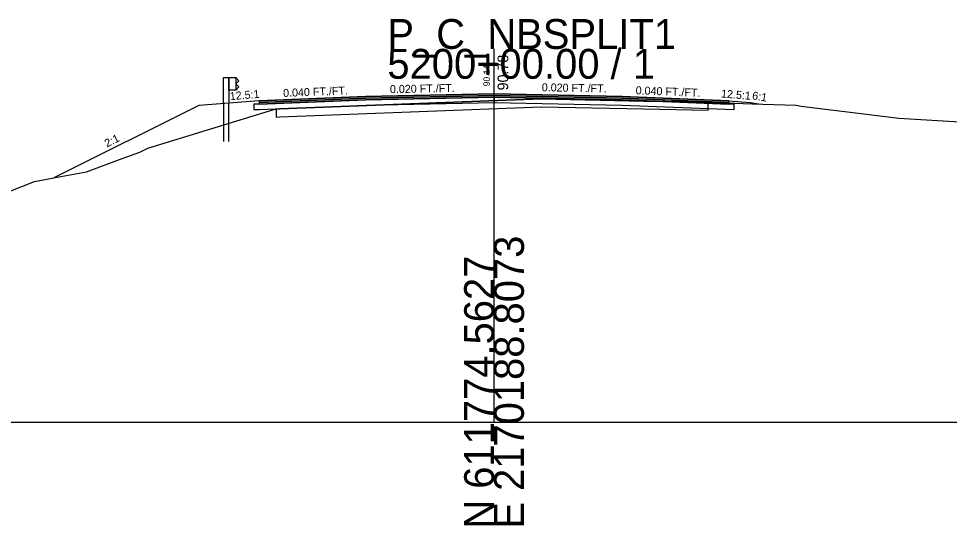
# Model space of a CAD drawing. Extents: x -26 to 1303, y -3010 to 12038.
# Drawn here: x 1105.4 to 1192.7, y 990.3 to 1037.8 of the extents above; entities that cross this region are included whole.
import ezdxf

# ---------------------------------------------------------------- set-up
doc = ezdxf.new("R2010")
doc.units = 0
for name, color, linetype in [('RD_GPK_XS_Cell', 7, 'Continuous'), ('RD_PD_Final_TrvlWay', 7, 'Continuous'), ('RD_XS_Base', 7, 'Continuous'), ('RD_XS_ExGround', 7, 'Continuous'), ('RD_XS_ExPaveRet', 7, 'Continuous'), ('RD_XS_GR', 7, 'Continuous'), ('RD_XS_Greenside', 7, 'Continuous'), ('RD_XS_Pave', 7, 'Continuous'), ('RD_XS_PaveOvlay_CP', 7, 'Continuous'), ('RD_XS_TieSlope', 7, 'Continuous'), ('RD_XS_TX_Elev_EX', 7, 'Continuous'), ('RD_XS_TX_Elev_PR', 7, 'Continuous'), ('RD_XS_TX_ShdSlope', 7, 'Continuous'), ('RD_XS_TX_Slope', 7, 'Continuous')]:
    doc.layers.add(name, color=color, linetype=linetype)

msp = doc.modelspace()

# ---------------------------------------------------------------- linework, layer by layer
at = {"layer": 'RD_GPK_XS_Cell'}
for p, q in [((1150, 1000), (1150, 1035)), ((1000, 1000), (1150, 1000)), ((1150, 1000), (1300, 1000))]:
    msp.add_line(p, q, dxfattribs=at)
at = {"layer": 'RD_PD_Final_TrvlWay'}
for p, q in [((1125.13, 1029.913), (1124.63, 1029.873)), ((1124.63, 1029.873), (1124.63, 1026.308)), ((1125.13, 1026.308), (1125.13, 1029.913))]:
    msp.add_line(p, q, dxfattribs=at)
at = {"layer": 'RD_XS_Base'}
for p, q in [((1138, 1030.224), (1128, 1029.824)), ((1150, 1030.464), (1138, 1030.224)), ((1138, 1030.224), (1138, 1030.224)), ((1150, 1030.464), (1150, 1030.623)), ((1150, 1030.623), (1150, 1030.623)), ((1150, 1030.623), (1150, 1030.623)), ((1150, 1030.623), (1150, 1029.964)), ((1150, 1029.964), (1150, 1030.464)), ((1150, 1030.464), (1150, 1030.464)), ((1150, 1030.464), (1150, 1030.464)), ((1150, 1030.464), (1150, 1030.464)), ((1162, 1030.224), (1150, 1030.464)), ((1172, 1029.824), (1162, 1030.224)), ((1128, 1029.824), (1127.5, 1029.804)), ((1127.5, 1029.804), (1127.5, 1029.804)), ((1127.5, 1029.804), (1127.5, 1029.304)), ((1127.5, 1029.304), (1128, 1029.324)), ((1128, 1029.824), (1128, 1029.824)), ((1128, 1029.324), (1138, 1029.724)), ((1128, 1029.324), (1128, 1029.324)), ((1138, 1029.724), (1150, 1029.964)), ((1138, 1029.724), (1138, 1029.724)), ((1150, 1029.964), (1150, 1029.964)), ((1150, 1029.964), (1150, 1029.964)), ((1150, 1029.964), (1162, 1029.724)), ((1162, 1029.724), (1172.5, 1029.304)), ((1164, 1030.144), (1164, 1030.144)), ((1164, 1029.644), (1164, 1029.644)), ((1172.5, 1029.804), (1172, 1029.824)), ((1172, 1029.824), (1172, 1029.824)), ((1172.5, 1029.304), (1172.5, 1029.804)), ((1172.5, 1029.804), (1172.5, 1029.804))]:
    msp.add_line(p, q, dxfattribs=at)
at = {"layer": 'RD_XS_ExGround'}
msp.add_lwpolyline([(1104.392, 1021.568), (1106.93, 1022.555), (1109.386, 1023.017), (1111.798, 1023.477), (1115.147, 1024.714), (1116.805, 1025.315), (1117.545, 1025.693), (1129.35, 1029.301), (1129.573, 1029.356), (1129.913, 1029.369), (1154.42, 1030.316), (1164.038, 1030.113), (1170.077, 1030.001), (1174.159, 1029.847), (1178.323, 1029.708), (1178.797, 1029.613), (1179.768, 1029.495), (1184.657, 1028.904), (1187.945, 1028.492), (1202.433, 1027.636)], dxfattribs=at)
at = {"layer": 'RD_XS_ExPaveRet'}
for p, q in [((1154.42, 1030.316), (1129.913, 1029.369)), ((1164.038, 1030.113), (1154.42, 1030.316)), ((1129.913, 1029.369), (1129.573, 1029.356)), ((1129.913, 1029.369), (1129.913, 1029.369)), ((1170.077, 1030.001), (1164.038, 1030.113))]:
    msp.add_line(p, q, dxfattribs=at)
for points in [[(1170.077, 1030.001), (1164.038, 1030.113), (1164.038, 1030.113), (1154.42, 1030.316), (1154.42, 1030.316), (1154.42, 1030.316), (1154.42, 1030.316), (1154.42, 1030.316), (1129.913, 1029.369), (1129.913, 1029.369), (1129.573, 1029.356), (1129.573, 1029.356), (1129.573, 1029.356), (1129.573, 1029.356), (1129.573, 1028.606), (1129.573, 1028.606), (1129.573, 1028.606), (1129.913, 1028.619), (1129.913, 1028.619), (1154.42, 1029.566), (1154.42, 1029.566), (1154.42, 1029.566), (1154.42, 1029.566), (1154.42, 1029.566), (1164.038, 1029.363), (1164.038, 1029.363), (1170.077, 1029.251), (1170.077, 1029.251), (1170.077, 1029.251), (1170.077, 1030.001), (1170.077, 1030.001)], [(1129.573, 1029.356), (1129.573, 1029.356), (1129.573, 1028.606), (1129.573, 1028.606), (1129.913, 1028.619), (1129.913, 1028.619), (1154.42, 1029.566), (1164.038, 1029.363), (1170.077, 1029.251), (1170.077, 1030.001)]]:
    msp.add_lwpolyline(points, dxfattribs=at)
at = {"layer": 'RD_XS_GR'}
for points in [[(1125.13, 1032.308), (1125.13, 1029.913), (1124.63, 1029.873), (1124.63, 1032.308), (1124.88, 1032.308), (1125.13, 1032.308)], [(1125.797, 1032.308), (1125.797, 1031.141), (1125.13, 1031.141), (1125.13, 1032.308), (1125.797, 1032.308)], [(1125.797, 1032.308), (1125.797, 1032.308), (1125.797, 1032.308), (1125.797, 1031.141), (1126.068, 1031.433), (1126.068, 1031.433), (1125.797, 1031.725), (1125.797, 1031.725), (1126.068, 1032.016), (1126.068, 1032.016), (1125.797, 1032.308)]]:
    msp.add_lwpolyline(points, dxfattribs=at)
at = {"layer": 'RD_XS_Greenside'}
for p, q in [((1122.318, 1029.688), (1108.729, 1022.893)), ((1174, 1029.982), (1174.975, 1029.82))]:
    msp.add_line(p, q, dxfattribs=at)
at = {"layer": 'RD_XS_Pave'}
for p, q in [((1138, 1030.542), (1128, 1030.142)), ((1138, 1030.383), (1128, 1029.983)), ((1128, 1029.983), (1138, 1030.383)), ((1128, 1029.824), (1138, 1030.224)), ((1150, 1030.782), (1138, 1030.542)), ((1150, 1030.623), (1138, 1030.383)), ((1138, 1030.383), (1150, 1030.623)), ((1138, 1030.542), (1138, 1030.542)), ((1138, 1030.224), (1150, 1030.464)), ((1138, 1030.383), (1138, 1030.383)), ((1138, 1030.383), (1138, 1030.383)), ((1138, 1030.224), (1138, 1030.224)), ((1162, 1030.542), (1150, 1030.782)), ((1150, 1030.782), (1150, 1030.782)), ((1150, 1030.782), (1150, 1030.782)), ((1150, 1030.464), (1150, 1030.623)), ((1150, 1030.623), (1150, 1030.623)), ((1150, 1030.623), (1150, 1030.623)), ((1150, 1030.623), (1150, 1030.623)), ((1150, 1030.623), (1150, 1030.623)), ((1150, 1030.623), (1162, 1030.383)), ((1162, 1030.383), (1150, 1030.623)), ((1150, 1030.623), (1150, 1030.623)), ((1150, 1030.623), (1150, 1030.623)), ((1150, 1030.623), (1150, 1030.464)), ((1150, 1030.464), (1150, 1030.464)), ((1150, 1030.464), (1150, 1030.464)), ((1150, 1030.464), (1162, 1030.224)), ((1172, 1030.142), (1162, 1030.542)), ((1162, 1030.383), (1172, 1029.983)), ((1172, 1029.983), (1162, 1030.383)), ((1162, 1030.224), (1172, 1029.824)), ((1164, 1030.462), (1164, 1030.462)), ((1164, 1030.303), (1164, 1030.303)), ((1164, 1030.303), (1164, 1030.303)), ((1128, 1030.142), (1128, 1030.142)), ((1128, 1030.142), (1128, 1029.983)), ((1128, 1029.983), (1128, 1029.983)), ((1128, 1029.983), (1128, 1029.824)), ((1164, 1030.144), (1164, 1030.144)), ((1172, 1029.983), (1172, 1030.142)), ((1172, 1030.142), (1172, 1030.142)), ((1172, 1029.824), (1172, 1029.983)), ((1172, 1029.983), (1172, 1029.983))]:
    msp.add_line(p, q, dxfattribs=at)
at = {"layer": 'RD_XS_PaveOvlay_CP'}
for p, q in [((1128, 1030.142), (1138, 1030.542)), ((1138, 1030.542), (1150, 1030.782)), ((1150, 1030.782), (1162, 1030.542)), ((1162, 1030.542), (1172, 1030.142))]:
    msp.add_line(p, q, dxfattribs=at)
at = {"layer": 'RD_XS_TieSlope'}
for p, q in [((1128, 1030.142), (1122.318, 1029.688)), ((1172, 1030.142), (1174, 1029.982))]:
    msp.add_line(p, q, dxfattribs=at)

# ---------------------------------------------------------------- texts
at = {"layer": 'RD_GPK_XS_Cell'}
for s, p in [('P_C_NBSPLIT1', (1140, 1035)), ('5200+00.00 / 1', (1140, 1032.2))]:
    msp.add_text(s, height=2.8, dxfattribs=at).set_placement(p)
for s, p in [('E 2170188.8073', (1152.8, 990)), ('N 611774.5627', (1150, 990))]:
    msp.add_text(s, height=2.8, rotation=90, dxfattribs=at).set_placement(p)
at = {"layer": 'RD_XS_TX_Elev_EX'}
msp.add_text('90.14', height=0.6, rotation=90, dxfattribs=at).set_placement((1149.604, 1031.493))
at = {"layer": 'RD_XS_TX_Elev_PR'}
msp.add_text('90.78', height=1, rotation=90, dxfattribs=at).set_placement((1151.328, 1031.11))
at = {"layer": 'RD_XS_TX_ShdSlope'}
for rotation, p in [(4.57392, (1125.262, 1030.187)), (355.42608, (1171.257, 1030.448))]:
    msp.add_text('12.5:1', height=0.75, rotation=rotation, dxfattribs=at).set_placement(p)
at = {"layer": 'RD_XS_TX_Slope'}
for s, rotation, p in [('0.040 FT./FT.', 2.29061, (1130.247, 1030.49)), ('0.020 FT./FT.', 1.14576, (1140.248, 1030.845)), ('0.020 FT./FT.', 358.85424, (1154.468, 1031.029)), ('0.040 FT./FT.', 357.70939, (1163.262, 1030.749)), ('6:1', 350.53582, (1174.149, 1030.28)), ('2:1', 26.56505, (1113.727, 1025.75))]:
    msp.add_text(s, height=0.75, rotation=rotation, dxfattribs=at).set_placement(p)

doc.saveas('drawing.dxf')
